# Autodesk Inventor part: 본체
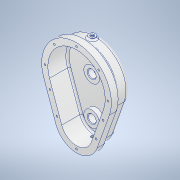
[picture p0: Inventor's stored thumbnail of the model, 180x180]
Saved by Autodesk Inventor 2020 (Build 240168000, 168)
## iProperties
Created: 2024-05
Part Number: 본체
Material: 알루미늄 6061
Document SubType Name: Modeling
Designer: oem
Density: 2.7 g/cm^3
Appearance: 알루미늄 - 평지
Mass: 508.765 g
Surface Area: 657.559 cm^2
Volume: 188.431 cm^3
Author: oem
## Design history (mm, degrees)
sketch "스케치1"
  geometry: L1 (0, 34)-(0, -35); L2 (-36.77, -48)-(-58.454, 13.333); L3 (36, -50.177)-(58.454, 13.333); A1 r 62 centre (0, 34) between (58.454, 13.333) and (-58.454, 13.333); A2 r 39 centre (0, -35) between (-36.77, -48) and (36.77, -48); 1 further point
  constraints: 6 end point, 4 point on circle, 4 tangent, 2 centre point, 2 coincident, 1 point on line, 1 vertical, 1 vertical alignment
  dimensions: "d3" = 62 radius of A1; "d4" = 39 radius of A2; "d134" = 34 distance of L1.start point (0, 0)
extrude "돌출1" new body sketch "스케치1" distance "d5" = 15; taper "d6" = 0 deg
sketch "스케치2"
  geometry: L1 (58.454, 13.333)-(36.77, -48) reference; L2 (-52.797, 15.333)-(-31.113, -46); L3 (31.113, -46)-(52.797, 15.333); A1 r 62 centre (0, 34) between (58.454, 13.333) and (-58.454, 13.333) reference; A2 r 39 centre (0, -35) between (-36.77, -48) and (36.77, -48) reference; A3 r 56 centre (0, 34) between (52.797, 15.333) and (-52.797, 15.333); A4 r 33 centre (0, -35) between (-31.113, -46) and (31.113, -46); 1 further point
  constraints: 4 end point, 4 point on circle, 3 tangent, 2 centre point, 2 coincident, 1 parallel
  dimensions: "d9" = 56 radius of A3; "d10" = 33 radius of A4
extrude "돌출2" join sketch "스케치2" distance "d11" = 25; taper "d12" = 0 deg
fillet "모깎기1" dims "d13" = 8
fillet "모깎기2" dims "d14" = 3
sketch "스케치3"
  geometry: C1 r 15 at (0, 34); A1 r 48 centre (0, 34) between (45.255, 18) and (-45.255, 18) reference; 1 further point
  constraints: 1 centre point, 1 coincident
  dimensions: "d16" = 30 diameter of C1
extrude "돌출3" join sketch "스케치3" distance "d17" = 8; taper "d18" = 0 deg
sketch "스케치4"
  geometry: C1 r 15 at (0, -35); A1 r 25 centre (0, -35) between (-23.57, -43.334) and (23.57, -43.334) reference; 1 further point
  constraints: 1 centre point, 1 coincident
  dimensions: "d19" = 30 diameter of C1
extrude "돌출4" join sketch "스케치4" distance "d20" = 8; taper "d21" = 0 deg
node "작업 평면1"
sketch "스케치12"
  geometry: C1 r 15 at (0, 34) reference; 2 further points
  constraints: 1 vertical alignment, 1 other
  dimensions: "d51" = 30 distance of C1.centre point (0, 64)
feature "엠보싱1" sketch "스케치12" dims "d3" = 62, "d4" = 39, "d11" = 25, "d12" = 0, "d52" = 0.5, "d53" = 0, "d134" = 34
sketch "스케치13"
  geometry: L1 (-26.399, -44.334)-(-48.083, 17); L2 (48.083, 17)-(26.399, -44.334); A1 r 39 centre (0, -35) between (-36.77, -48) and (36.77, -48) reference; A2 r 62 centre (0, 34) between (58.454, 13.333) and (-58.454, 13.333) reference; A3 r 28 centre (0, -35) between (-26.399, -44.334) and (26.399, -44.334); A4 r 51 centre (0, 34) between (48.083, 17) and (-48.083, 17); 1 further point
  constraints: 4 end point, 4 point on circle, 4 tangent, 2 centre point, 2 coincident
  dimensions: "d56" = 51 radius of A4; "d57" = 28 radius of A3
extrude "돌출7" cut sketch "스케치13" distance "d58" = 35; taper "d59" = 0 deg
sketch "스케치14"
  geometry: C1 r 14 at (0, 34); A1 r 51 centre (0, 34) between (48.083, 17) and (-48.083, 17) reference; 1 further point
  constraints: 1 centre point, 1 coincident
  dimensions: "d60" = 28 diameter of C1
extrude "돌출8" join sketch "스케치14" distance "d61" = 8; taper "d62" = 0 deg
sketch "스케치15"
  geometry: C1 r 14 at (0, -35); A1 r 28 centre (0, -35) between (-26.399, -44.334) and (26.399, -44.334) reference; 1 further point
  constraints: 1 centre point, 1 coincident
  dimensions: "d64" = 28 diameter of C1
extrude "돌출9" join sketch "스케치15" distance "d65" = 8; taper "d66" = 0 deg
fillet "모깎기3" dims "d67" = 3
sketch "스케치16"
  geometry: C1 r 15 at (0, 0) reference; 2 further points
  constraints: 1 coincident
hole "구멍4" sketch "스케치16" at (0, 0) diameter "d68" = 14; stored, may be unused: countersink angle "d72" = 90 deg, drill point angle "d74" = 0 deg; dims "d69" = 24, "d70" = 20, "d71" = 4.2, "d73" = 10
sketch "스케치17"
  geometry: C1 r 14 at (0, 0) reference; 2 further points
  constraints: 1 coincident
hole "구멍5" sketch "스케치17" at (0, 0) diameter "d75" = 14; stored, may be unused: countersink angle "d79" = 90 deg, drill point angle "d81" = 0 deg; dims "d76" = 24, "d77" = 20, "d78" = 4.2, "d80" = 10
sketch "스케치18"
  geometry: L1 (-31.113, -46)-(-52.797, 15.333); L2 (31.113, -46)-(52.797, 15.333); L3 (0, 34)-(0, 90); L4 (0, 34)-(39.598, 73.598); L5 (0, 34)-(-39.598, 73.598); L6 (52.797, 15.333)-(31.113, -46) reference; L7 (-31.113, -46)-(-52.797, 15.333) reference; C1 r 7 at (0, 34) reference; A1 r 51 centre (0, 34) between (48.083, 17) and (-48.083, 17) reference; A2 r 28 centre (0, -35) between (-26.399, -44.334) and (26.399, -44.334) reference; A3 r 39 centre (0, -35) between (-36.77, -48) and (36.77, -48) reference; A4 r 33 centre (0, -35) between (-31.113, -46) and (31.113, -46) reference; A5 r 56 centre (0, 34) between (52.797, 15.333) and (-52.797, 15.333) reference; A6 r 33 centre (0, -35) between (-31.113, -46) and (31.113, -46); A7 r 56 centre (0, 34) between (52.797, 15.333) and (-52.797, 15.333); 11 further points
  constraints: 10 end point, 10 point on circle, 6 horizontal alignment, 5 coincident, 4 point on line, 3 tangent, 2 centre point
  dimensions: "d84" = 45 deg angle of L5 L3; "d85" = 45 deg angle of L3 L4
hole "구멍6" sketch "스케치18" at (-39.598, 73.598), (39.598, 73.598), (0, 90), (-56, 34), (56, 34), (35.002, -35), (-47.376, 0), (0, -68), (47.376, 0), (-35.002, -35) diameter "d86" = 3.242; stored, may be unused: countersink angle "d90" = 90 deg, drill point angle "d92" = 118 deg; dims "d87" = 8, "d88" = 20, "d89" = 4.2, "d91" = 10
node "작업 평면2"
sketch "스케치19"
  geometry: L1 (62, 0)-(-62, 0) reference; L2 (62, 15)-(-62, 15) reference; C1 r 6 at (0, -13); 6 further points
  constraints: 1 centre point, 1 midpoint, 1 vertical alignment
  dimensions: "d94" = 12 diameter of C1; "d95" = 28 distance from line of C1.centre L2
extrude "돌출10" join sketch "스케치19" stored distance "d96" = 8; taper "d97" = 0 deg
sketch "스케치20"
  geometry: C1 r 6 at (0, 0) reference; 2 further points
  constraints: 1 coincident
hole "구멍7" sketch "스케치20" at (0, 0) diameter "d98" = 5.1881; stored, may be unused: countersink angle "d102" = 90 deg, drill point angle "d104" = 0 deg; dims "d99" = 24.75, "d100" = 7, "d101" = 2, "d103" = 25.75
node "작업 평면3"
sketch "스케치21"
  geometry: L1 (-36.77, 15)-(36.77, 15) reference; L2 (-36.77, 0)-(36.77, 0) reference; C1 r 6 at (0, -13); 2 further points
  constraints: 1 centre point, 1 midpoint, 1 vertical alignment
  dimensions: "d106" = 12 diameter of C1; "d107" = 28 distance from line of L1 C1.centre
extrude "돌출11" join sketch "스케치21" stored distance "d108" = 8; taper "d109" = 0 deg
sketch "스케치22"
  geometry: C1 r 6 at (0, 0) reference; 2 further points
  constraints: 1 coincident
hole "구멍8" sketch "스케치22" at (0, 0) diameter "d110" = 5.1881; stored, may be unused: countersink angle "d114" = 90 deg, drill point angle "d116" = 0 deg; dims "d111" = 13.75, "d112" = 7, "d113" = 2, "d115" = 15.25
chamfer "모따기1" distance "d117" = 1; stored, may be unused: second distance "d118" = 2, angle "d119" = 45 deg
fillet "모깎기4" dims "d121" = 3
chamfer "모따기2" distance "d122" = 0.4; stored, may be unused: second distance "d123" = 2, angle "d124" = 30 deg
sketch "스케치24"
  geometry: L1 (41, -22)-(27, -22) reference; L2 (34, -22)-(38, -22); L3 (38, -22)-(34, -24.309); L4 (34, -24.309)-(34, -22); 1 further point
  constraints: 6 end point, 1 midpoint, 1 perpendicular, 1 point on line
  dimensions: "d127" = 60 deg angle of L3 L4; "d128" = 8 diameter of L2.end L4
revolve "회전1" sketch "스케치24" stored, may be unused: angle "d129" = 90 deg
fillet "모깎기5" dims "d130" = 3
fillet "모깎기6" dims "d131" = 3
fillet "모깎기7" dims "d132" = 3
fillet "모깎기8" dims "d133" = 3
fillet "모깎기9" dims "d135" = 0.1
node "솔리드1"
node "투영된 루프1"
feature "A9D066F2-1C7D-4E18-AEED-F7BC21143FA4" dims "d68" = 14, "d69" = 24, "d70" = 20, "d71" = 4.2, "d72" = 90 deg, "d73" = 10, "d74" = 0
other parameters: "d1" = 124, "d2" = 78, "d7" = 112, "d8" = 66, "d54" = 102, "d55" = 56, "d82" = 112, "d83" = 66, "d93" = 93, "d105" = -71
